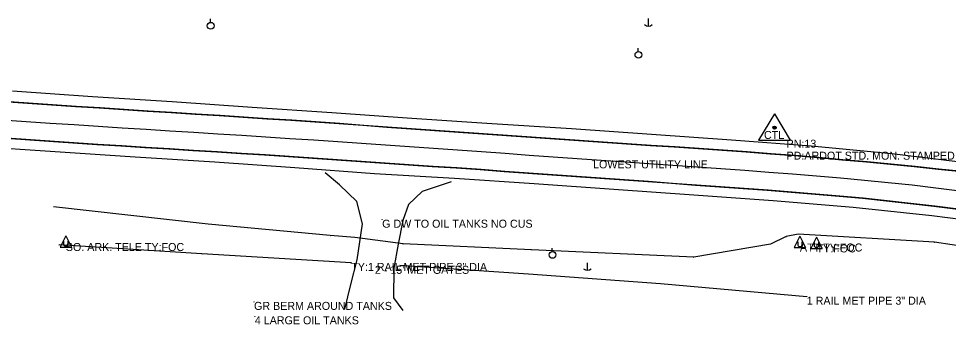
# Model space of a CAD drawing. Extents: x 878399 to 889864, y 1564003 to 1567413.
# Drawn here: x 881491 to 882072, y 1567067 to 1567258 of the extents above; entities that cross this region are included whole.
import ezdxf

# ---------------------------------------------------------------- set-up
doc = ezdxf.new("R2010")
doc.units = 0
for name, color, linetype in [('S_DRIVEWAY', 7, 'Continuous'), ('S_EDGE_PAVEMENT', 7, 'Continuous'), ('S_ELECTRIC_UTILITIES_ANNOT', 7, 'Continuous'), ('S_FENCE', 7, 'Continuous'), ('S_FENCE_ANNOT', 7, 'Continuous'), ('S_FIBER_OPTIC_CABLE', 7, 'Continuous'), ('S_GATE_ANNOT', 7, 'Continuous'), ('S_MSC_PT_SYM', 7, 'Continuous'), ('S_PAVEMENT_CROWN', 7, 'Continuous'), ('S_PRIMARY_CTL', 7, 'Continuous'), ('S_PRIMARY_CTL_ANNOT', 7, 'Continuous'), ('S_SHOULDER', 7, 'Continuous'), ('S_SURVEY_TEXT_ANNOT', 7, 'Continuous'), ('S_UTILITY_POLE', 7, 'Continuous'), ('S_UTILITY_POLE_ANNOT', 7, 'Continuous'), ('S_UTL_PT_SYM', 7, 'Continuous')]:
    doc.layers.add(name, color=color, linetype=linetype)

msp = doc.modelspace()

# ---------------------------------------------------------------- linework, layer by layer
at = {"layer": 'S_DRIVEWAY'}
for points in [[(881695.15, 1567076.39), (881699.05, 1567091.79), (881702.96, 1567107.2), (881706.21, 1567129.74), (881702.77, 1567143.66), (881691.81, 1567154.08), (881682.91, 1567161.56)], [(881761.58, 1567155.86), (881743.44, 1567149.84), (881735.05, 1567141.72), (881731.44, 1567131.81), (881728.59, 1567116.91), (881725.74, 1567102.01), (881725.7, 1567083.38), (881731.53, 1567075.58)]]:
    msp.add_lwpolyline(points, dxfattribs=at)
at = {"layer": 'S_EDGE_PAVEMENT'}
for points in [[(881481.93, 1567206.16), (881496.9, 1567205.15), (881511.85, 1567204.13), (881526.82, 1567203.12), (881541.79, 1567202.12), (881556.76, 1567201.16), (881571.73, 1567200.2), (881586.7, 1567199.23), (881601.67, 1567198.29), (881616.64, 1567197.35), (881631.59, 1567196.41), (881646.56, 1567195.42), (881661.53, 1567194.41), (881676.49, 1567193.41), (881691.46, 1567192.37), (881706.42, 1567191.27), (881706.42, 1567191.27), (881721.38, 1567190.17), (881721.38, 1567190.17), (881721.38, 1567190.17), (881736.34, 1567189.07), (881751.31, 1567188.02), (881766.27, 1567186.98), (881781.24, 1567185.94), (881796.27, 1567184.9), (881811.23, 1567183.88), (881826.2, 1567182.87), (881826.2, 1567182.87), (881841.17, 1567181.84), (881841.17, 1567181.84), (881856.13, 1567180.82), (881856.13, 1567180.82), (881856.13, 1567180.82), (881871.1, 1567179.79), (881886.06, 1567178.76), (881901.03, 1567177.77), (881916, 1567176.77), (881930.97, 1567175.77), (881946.02, 1567174.68), (881946.02, 1567174.68), (881960.98, 1567173.54), (881960.98, 1567173.54), (881960.98, 1567173.54), (881975.94, 1567172.4), (881975.94, 1567172.4), (881975.94, 1567172.4), (881990.89, 1567171.19), (881990.89, 1567171.19), (882005.83, 1567169.81), (882005.83, 1567169.81), (882005.83, 1567169.81), (882021.07, 1567168.41), (882021.07, 1567168.41), (882021.07, 1567168.41), (882036.01, 1567167.03), (882036.01, 1567167.03), (882050.94, 1567165.48), (882065.86, 1567163.92), (882080.78, 1567162.37)], [(881482.52, 1567206.35), (881497.48, 1567205.34), (881512.43, 1567204.33), (881527.4, 1567203.31), (881542.37, 1567202.31), (881557.34, 1567201.35), (881572.31, 1567200.39), (881587.28, 1567199.43), (881602.25, 1567198.48), (881617.22, 1567197.54), (881632.17, 1567196.6), (881647.14, 1567195.62), (881662.1, 1567194.61), (881677.07, 1567193.6), (881692.03, 1567192.56), (881706.99, 1567191.46), (881706.99, 1567191.46), (881721.95, 1567190.36), (881721.95, 1567190.36), (881721.95, 1567190.36), (881736.91, 1567189.26), (881751.88, 1567188.22), (881766.84, 1567187.17), (881781.81, 1567186.13), (881796.84, 1567185.1), (881811.8, 1567184.08), (881826.77, 1567183.06), (881826.77, 1567183.06), (881841.73, 1567182.04), (881841.73, 1567182.04), (881856.7, 1567181.01), (881856.7, 1567181.01), (881856.7, 1567181.01), (881871.66, 1567179.98), (881886.63, 1567178.96), (881901.6, 1567177.96), (881916.56, 1567176.96), (881931.53, 1567175.96), (881946.58, 1567174.87), (881946.58, 1567174.87), (881961.54, 1567173.73), (881961.54, 1567173.73), (881961.54, 1567173.73), (881976.5, 1567172.6), (881976.5, 1567172.6), (881976.5, 1567172.6), (881991.45, 1567171.39), (881991.45, 1567171.39), (882006.39, 1567170.01), (882006.39, 1567170.01), (882006.39, 1567170.01), (882021.63, 1567168.6), (882021.63, 1567168.6), (882021.63, 1567168.6), (882036.57, 1567167.23), (882036.57, 1567167.23), (882051.49, 1567165.68), (882066.41, 1567164.12), (882081.33, 1567162.57)], [(881480.38, 1567183.37), (881495.35, 1567182.36), (881510.33, 1567181.35), (881525.3, 1567180.36), (881540.27, 1567179.39), (881555.24, 1567178.42), (881570.21, 1567177.46), (881585.18, 1567176.55), (881600.16, 1567175.63), (881615.13, 1567174.71), (881630.12, 1567173.74), (881645.09, 1567172.77), (881660.06, 1567171.8), (881675.03, 1567170.76), (881689.99, 1567169.69), (881704.96, 1567168.63), (881719.92, 1567167.6), (881734.89, 1567166.62), (881749.86, 1567165.64), (881764.83, 1567164.65), (881779.79, 1567163.58), (881794.67, 1567162.52), (881809.64, 1567161.45), (881824.6, 1567160.37), (881839.56, 1567159.3), (881854.53, 1567158.23), (881869.49, 1567157.16), (881884.45, 1567156.09), (881899.41, 1567155.03), (881914.38, 1567153.96), (881929.34, 1567152.88), (881944.19, 1567151.8), (881959.15, 1567150.71), (881974.11, 1567149.52), (881989.06, 1567148.28), (882004.01, 1567147.04), (882018.57, 1567145.69), (882033.48, 1567144.03), (882048.39, 1567142.38), (882063.3, 1567140.72), (882078.18, 1567138.83)], [(881480.96, 1567183.56), (881495.93, 1567182.55), (881510.91, 1567181.54), (881525.88, 1567180.56), (881540.85, 1567179.58), (881555.82, 1567178.61), (881570.79, 1567177.66), (881585.76, 1567176.74), (881600.73, 1567175.83), (881615.71, 1567174.91), (881630.7, 1567173.93), (881645.67, 1567172.96), (881660.64, 1567171.99), (881675.6, 1567170.96), (881690.57, 1567169.89), (881705.53, 1567168.82), (881720.49, 1567167.79), (881735.46, 1567166.81), (881750.43, 1567165.83), (881765.4, 1567164.85), (881780.36, 1567163.78), (881795.24, 1567162.71), (881810.2, 1567161.64), (881825.17, 1567160.57), (881840.13, 1567159.5), (881855.09, 1567158.42), (881870.05, 1567157.35), (881885.02, 1567156.29), (881899.98, 1567155.22), (881914.94, 1567154.16), (881929.9, 1567153.07), (881944.75, 1567152), (881959.71, 1567150.91), (881974.66, 1567149.72), (881989.61, 1567148.48), (882004.56, 1567147.24), (882019.12, 1567145.88), (882034.03, 1567144.23), (882048.94, 1567142.58), (882063.85, 1567140.92), (882078.73, 1567139.03)]]:
    msp.add_lwpolyline(points, dxfattribs=at)
at = {"layer": 'S_FENCE'}
for p, q in [((881605.92, 1567111), (881516.71, 1567116.53)), ((881699.22, 1567105.28), (881605.92, 1567111)), ((881810.01, 1567098.27), (881729.55, 1567103.66)), ((881892.43, 1567092.24), (881810.01, 1567098.27)), ((881983.85, 1567084.19), (881892.43, 1567092.24))]:
    msp.add_line(p, q, dxfattribs=at)
at = {"layer": 'S_FIBER_OPTIC_CABLE'}
for p, q in [((881609.82, 1567129.54), (881513.12, 1567140.37)), ((881686.13, 1567122.45), (881609.82, 1567129.54)), ((881701.44, 1567121.22), (881686.13, 1567122.45)), ((881731.57, 1567117.12), (881701.44, 1567121.22)), ((881971.03, 1567121.87), (881961.16, 1567116.98)), ((881978.47, 1567123.31), (881971.03, 1567121.87)), ((882063.57, 1567118.17), (881978.47, 1567123.31)), ((882146.98, 1567105.69), (882063.57, 1567118.17)), ((881811.79, 1567113.4), (881731.57, 1567117.12)), ((881913.21, 1567108.95), (881811.79, 1567113.4)), ((881961.16, 1567116.98), (881913.21, 1567108.95))]:
    msp.add_line(p, q, dxfattribs=at)
at = {"layer": 'S_MSC_PT_SYM'}
for points in [[(881718.52, 1567132.29), (881718.52, 1567132.34), (881718.52, 1567132.29), (881718.47, 1567132.29), (881718.52, 1567132.29), (881718.52, 1567132.24), (881718.52, 1567132.29), (881718.57, 1567132.29)], [(881516.71, 1567116.53), (881516.71, 1567116.58), (881516.71, 1567116.53), (881516.66, 1567116.53), (881516.71, 1567116.53), (881516.71, 1567116.48), (881516.71, 1567116.53), (881516.76, 1567116.53)], [(881605.92, 1567111), (881605.92, 1567111.05), (881605.92, 1567111), (881605.87, 1567111), (881605.92, 1567111), (881605.92, 1567110.95), (881605.92, 1567111), (881605.97, 1567111)], [(881699.22, 1567105.28), (881699.22, 1567105.33), (881699.22, 1567105.28), (881699.17, 1567105.28), (881699.22, 1567105.28), (881699.22, 1567105.23), (881699.22, 1567105.28), (881699.27, 1567105.28)], [(881713.98, 1567103.47), (881713.98, 1567103.52), (881713.98, 1567103.47), (881713.93, 1567103.47), (881713.98, 1567103.47), (881713.98, 1567103.42), (881713.98, 1567103.47), (881714.03, 1567103.47)], [(881729.55, 1567103.66), (881729.55, 1567103.71), (881729.55, 1567103.66), (881729.5, 1567103.66), (881729.55, 1567103.66), (881729.55, 1567103.61), (881729.55, 1567103.66), (881729.6, 1567103.66)], [(881810.01, 1567098.27), (881810.01, 1567098.32), (881810.01, 1567098.27), (881809.96, 1567098.27), (881810.01, 1567098.27), (881810.01, 1567098.22), (881810.01, 1567098.27), (881810.06, 1567098.27)], [(881892.43, 1567092.24), (881892.43, 1567092.29), (881892.43, 1567092.24), (881892.38, 1567092.24), (881892.43, 1567092.24), (881892.43, 1567092.19), (881892.43, 1567092.24), (881892.48, 1567092.24)], [(881983.85, 1567084.19), (881983.85, 1567084.24), (881983.85, 1567084.19), (881983.8, 1567084.19), (881983.85, 1567084.19), (881983.85, 1567084.14), (881983.85, 1567084.19), (881983.9, 1567084.19)], [(881638.45, 1567080.93), (881638.45, 1567080.98), (881638.45, 1567080.93), (881638.4, 1567080.93), (881638.45, 1567080.93), (881638.45, 1567080.88), (881638.45, 1567080.93), (881638.5, 1567080.93)], [(881638.95, 1567071.93), (881638.95, 1567071.98), (881638.95, 1567071.93), (881638.9, 1567071.93), (881638.95, 1567071.93), (881638.95, 1567071.88), (881638.95, 1567071.93), (881639, 1567071.93)]]:
    msp.add_lwpolyline(points, dxfattribs=at)
at = {"layer": 'S_PAVEMENT_CROWN'}
msp.add_lwpolyline([(881481.15, 1567194.7), (881496.12, 1567193.7), (881511.09, 1567192.71), (881526.06, 1567191.73), (881541.03, 1567190.74), (881541.03, 1567190.74), (881541.03, 1567190.74), (881556, 1567189.79), (881556, 1567189.79), (881570.97, 1567188.84), (881570.97, 1567188.84), (881585.94, 1567187.88), (881585.94, 1567187.88), (881585.94, 1567187.88), (881600.91, 1567186.94), (881600.91, 1567186.94), (881615.88, 1567186.01), (881615.88, 1567186.01), (881630.86, 1567185.07), (881645.83, 1567184.13), (881645.83, 1567184.13), (881660.8, 1567183.14), (881660.8, 1567183.14), (881660.8, 1567183.14), (881675.77, 1567182.15), (881675.77, 1567182.15), (881690.73, 1567181.15), (881690.73, 1567181.15), (881705.7, 1567180.12), (881705.7, 1567180.12), (881720.66, 1567179.07), (881735.63, 1567178.02), (881750.59, 1567176.97), (881765.56, 1567175.9), (881780.52, 1567174.84), (881780.52, 1567174.84), (881795.48, 1567173.77), (881795.48, 1567173.77), (881810.44, 1567172.69), (881810.44, 1567172.69), (881825.4, 1567171.61), (881825.4, 1567171.61), (881825.4, 1567171.61), (881840.36, 1567170.53), (881855.33, 1567169.49), (881870.29, 1567168.45), (881870.29, 1567168.45), (881885.26, 1567167.41), (881900.22, 1567166.37), (881900.22, 1567166.37), (881915.19, 1567165.33), (881930.15, 1567164.29), (881930.15, 1567164.29), (881930.15, 1567164.29), (881945.11, 1567163.23), (881960.06, 1567162.08), (881960.06, 1567162.08), (881975.02, 1567160.93), (881989.98, 1567159.78), (881989.98, 1567159.78), (882004.92, 1567158.41), (882004.92, 1567158.41), (882019.82, 1567157), (882034.75, 1567155.59), (882034.75, 1567155.59), (882049.67, 1567153.98), (882049.67, 1567153.98), (882064.56, 1567152.19), (882079.46, 1567150.4)], dxfattribs=at)
at = {"layer": 'S_PRIMARY_CTL'}
for p, q in [((881963.69, 1567198.51), (881953.66, 1567182)), ((881963.69, 1567198.51), (881973.52, 1567182)), ((881953.66, 1567182), (881973.52, 1567182))]:
    msp.add_line(p, q, dxfattribs=at)
for radius in [1.04, 0.609, 0.344]:
    msp.add_circle((881963.69, 1567189.81), radius, dxfattribs=at)
at = {"layer": 'S_SHOULDER'}
for points in [[(881487.59, 1567212.73), (881537.45, 1567209.26), (881587.35, 1567206.06), (881637.21, 1567202.67), (881687.1, 1567199.29), (881736.97, 1567195.68), (881786.98, 1567192.5), (881836.88, 1567189.22), (881886.76, 1567185.75), (881936.79, 1567182.19), (881986.66, 1567178.44), (882036.94, 1567173.62), (882086.58, 1567167.54)], [(881464.3, 1567178.2), (881514.23, 1567174.95), (881564.11, 1567171.56), (881614.01, 1567168.36), (881663.93, 1567164.87), (881713.81, 1567161.26), (881763.72, 1567158.17), (881813.49, 1567154.92), (881863.36, 1567151.28), (881913.24, 1567147.75), (881962.95, 1567144.19), (882012.8, 1567140.2), (882061.97, 1567134.99), (882110.92, 1567128.57)]]:
    msp.add_lwpolyline(points, dxfattribs=at)
at = {"layer": 'S_UTILITY_POLE'}
for p, q in [((881611.26, 1567255.63), (881611.26, 1567257.73)), ((881884.82, 1567257.97), (881884.82, 1567253.24)), ((881878.54, 1567237.45), (881878.54, 1567239.56)), ((881520.86, 1567122.27), (881517.33, 1567115.18)), ((881519.65, 1567116.42), (881519.65, 1567118.86)), ((881520.86, 1567122.27), (881524.34, 1567115.18)), ((881522.02, 1567118.86), (881522.02, 1567116.42)), ((881979.57, 1567121.95), (881976.04, 1567114.86)), ((881978.37, 1567116.1), (881978.37, 1567118.54)), ((881979.57, 1567121.95), (881983.06, 1567114.86)), ((881980.73, 1567118.54), (881980.73, 1567116.1)), ((881989.97, 1567121.37), (881986.44, 1567114.28)), ((881988.77, 1567115.52), (881988.77, 1567117.96)), ((881989.97, 1567121.37), (881993.45, 1567114.28)), ((881991.13, 1567117.96), (881991.13, 1567115.52)), ((881517.33, 1567115.18), (881524.34, 1567115.18)), ((881520.27, 1567115.76), (881519.65, 1567116.42)), ((881521.48, 1567115.76), (881520.27, 1567115.76)), ((881522.02, 1567116.42), (881521.48, 1567115.76)), ((881824.83, 1567112.45), (881824.83, 1567114.55)), ((881976.04, 1567114.86), (881983.06, 1567114.86)), ((881978.99, 1567115.44), (881978.37, 1567116.1)), ((881980.19, 1567115.44), (881978.99, 1567115.44)), ((881980.73, 1567116.1), (881980.19, 1567115.44)), ((881986.44, 1567114.28), (881993.45, 1567114.28)), ((881989.39, 1567114.86), (881988.77, 1567115.52)), ((881990.59, 1567114.86), (881989.39, 1567114.86)), ((881991.13, 1567115.52), (881990.59, 1567114.86)), ((881846.72, 1567105.42), (881846.72, 1567100.69))]:
    msp.add_line(p, q, dxfattribs=at)
for centre in [(881611.38, 1567253.48), (881878.66, 1567235.31), (881824.95, 1567110.31)]:
    msp.add_circle(centre, 2.13, dxfattribs=at)
for centre in [(881884.88, 1567256.67), (881846.78, 1567104.12)]:
    msp.add_arc(centre, 3.41, 226.39718, 313.60282, dxfattribs=at)
at = {"layer": 'S_UTL_PT_SYM'}
for points in [[(881850.3, 1567169.37), (881850.3, 1567169.42), (881850.3, 1567169.37), (881850.25, 1567169.37), (881850.3, 1567169.37), (881850.3, 1567169.32), (881850.3, 1567169.37), (881850.35, 1567169.37)], [(881513.12, 1567140.37), (881513.12, 1567140.42), (881513.12, 1567140.37), (881513.07, 1567140.37), (881513.12, 1567140.37), (881513.12, 1567140.32), (881513.12, 1567140.37), (881513.17, 1567140.37)], [(881609.82, 1567129.54), (881609.82, 1567129.59), (881609.82, 1567129.54), (881609.77, 1567129.54), (881609.82, 1567129.54), (881609.82, 1567129.49), (881609.82, 1567129.54), (881609.87, 1567129.54)], [(881686.13, 1567122.45), (881686.13, 1567122.5), (881686.13, 1567122.45), (881686.08, 1567122.45), (881686.13, 1567122.45), (881686.13, 1567122.4), (881686.13, 1567122.45), (881686.18, 1567122.45)], [(881701.44, 1567121.22), (881701.44, 1567121.27), (881701.44, 1567121.22), (881701.39, 1567121.22), (881701.44, 1567121.22), (881701.44, 1567121.17), (881701.44, 1567121.22), (881701.49, 1567121.22)], [(881971.03, 1567121.87), (881971.03, 1567121.92), (881971.03, 1567121.87), (881970.98, 1567121.87), (881971.03, 1567121.87), (881971.03, 1567121.82), (881971.03, 1567121.87), (881971.08, 1567121.87)], [(881978.47, 1567123.31), (881978.47, 1567123.36), (881978.47, 1567123.31), (881978.42, 1567123.31), (881978.47, 1567123.31), (881978.47, 1567123.26), (881978.47, 1567123.31), (881978.52, 1567123.31)], [(882063.57, 1567118.17), (882063.57, 1567118.22), (882063.57, 1567118.17), (882063.52, 1567118.17), (882063.57, 1567118.17), (882063.57, 1567118.12), (882063.57, 1567118.17), (882063.62, 1567118.17)], [(881731.57, 1567117.12), (881731.57, 1567117.17), (881731.57, 1567117.12), (881731.52, 1567117.12), (881731.57, 1567117.12), (881731.57, 1567117.07), (881731.57, 1567117.12), (881731.62, 1567117.12)], [(881811.79, 1567113.4), (881811.79, 1567113.45), (881811.79, 1567113.4), (881811.74, 1567113.4), (881811.79, 1567113.4), (881811.79, 1567113.35), (881811.79, 1567113.4), (881811.84, 1567113.4)], [(881961.16, 1567116.98), (881961.16, 1567117.03), (881961.16, 1567116.98), (881961.11, 1567116.98), (881961.16, 1567116.98), (881961.16, 1567116.93), (881961.16, 1567116.98), (881961.21, 1567116.98)], [(881913.21, 1567108.95), (881913.21, 1567109), (881913.21, 1567108.95), (881913.16, 1567108.95), (881913.21, 1567108.95), (881913.21, 1567108.9), (881913.21, 1567108.95), (881913.26, 1567108.95)]]:
    msp.add_lwpolyline(points, dxfattribs=at)

# ---------------------------------------------------------------- texts
at = {"layer": 'S_ELECTRIC_UTILITIES_ANNOT'}
msp.add_text('LOWEST UTILITY LINE ', height=5, dxfattribs=at).set_placement((881850.3, 1567164.37))
at = {"layer": 'S_FENCE_ANNOT'}
for s, p in [('TY:1 RAIL MET PIPE 3" DIA', (881699.22, 1567100.28)), ('1 RAIL MET PIPE 3" DIA', (881983.85, 1567079.19))]:
    msp.add_text(s, height=5, dxfattribs=at).set_placement(p)
at = {"layer": 'S_GATE_ANNOT'}
msp.add_text("2 - 15' MET GATES", height=5, dxfattribs=at).set_placement((881713.98, 1567098.47))
at = {"layer": 'S_PRIMARY_CTL'}
msp.add_text('CTL', height=5, rotation=360, dxfattribs=at).set_placement((881957.11, 1567182.74))
at = {"layer": 'S_PRIMARY_CTL_ANNOT'}
for s, p in [('PN:13', (881971.19, 1567177.31)), ('PD:ARDOT STD. MON. STAMPED PN:13', (881971.19, 1567169.81))]:
    msp.add_text(s, height=5, dxfattribs=at).set_placement(p)
at = {"layer": 'S_SURVEY_TEXT_ANNOT'}
for s, p in [('G DW TO OIL TANKS NO CUS', (881718.52, 1567127.29)), ('GR BERM AROUND TANKS', (881638.45, 1567075.93)), ('4 LARGE OIL TANKS', (881638.95, 1567066.93))]:
    msp.add_text(s, height=5, dxfattribs=at).set_placement(p)
at = {"layer": 'S_UTILITY_POLE_ANNOT'}
for s, p in [('SO. ARK. TELE TY:FOC', (881520.86, 1567112.73)), ('ATT TY:FOC', (881979.57, 1567112.42)), ('TY:FOC', (881989.97, 1567111.84))]:
    msp.add_text(s, height=5, dxfattribs=at).set_placement(p)

doc.saveas('drawing.dxf')
